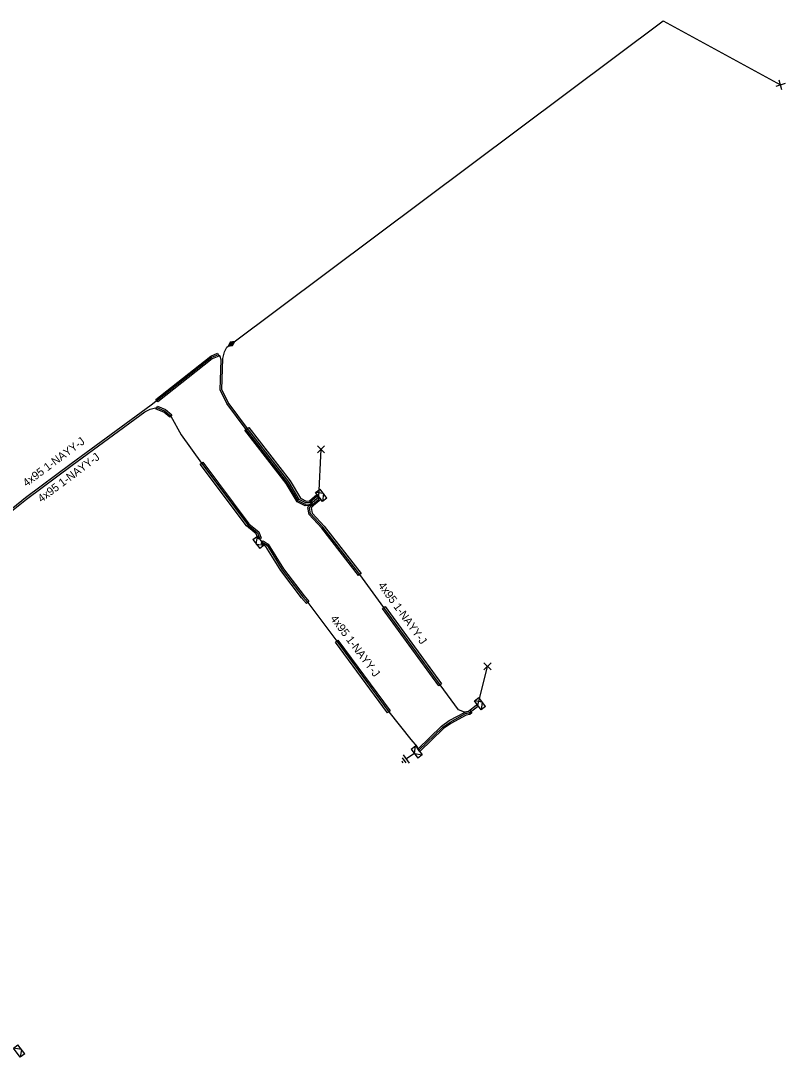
# Model space of a CAD drawing. Extents: x -544780 to -541582, y -1198995 to -1196551.
# Drawn here: x -543484.1 to -543388.6, y -1197308.9 to -1197179.5 of the extents above; entities that cross this region are included whole.
import ezdxf

# ---------------------------------------------------------------- set-up
doc = ezdxf.new("R2010")
doc.units = 0
for name, color, linetype in [('Vrstva 1', 7, 'Continuous'), ('Vrstva 14', 7, 'Continuous'), ('Vrstva 15', 7, 'Continuous'), ('Vrstva 19', 7, 'Continuous'), ('Vrstva 20', 7, 'Continuous'), ('Vrstva 31', 7, 'Continuous'), ('Vrstva 34', 7, 'Continuous'), ('Vrstva 4', 7, 'Continuous'), ('Vrstva 5', 7, 'Continuous'), ('Vrstva 52', 7, 'Continuous'), ('Vrstva 59', 7, 'Continuous'), ('Vrstva 6', 7, 'Continuous'), ('Vrstva 9', 7, 'Continuous')]:
    doc.layers.add(name, color=color, linetype=linetype)

# ---------------------------------------------------------------- blocks, each defined once
blk = doc.blocks.new('NN870')
at = {"layer": 'Vrstva 4'}
for points in [[(0, -0.25), (0.5, 0), (0, 0.25), (-0.5, 0), (0, -0.25)], [(0.37, 0), (0, 0.19), (-0.36, 0), (0, -0.19), (0.37, 0)], [(0.24, 0), (0, 0.12), (-0.25, 0), (0, -0.12), (0.24, 0)], [(0.12, 0), (0, 0.06), (-0.13, 0), (0, -0.06), (0.12, 0)]]:
    blk.add_lwpolyline(points, dxfattribs=at)
blk = doc.blocks.new('NN800')
at = {"layer": 'Vrstva 1'}
for points in [[(-0.44, 0.44), (0.44, -0.44)], [(-0.44, -0.44), (0.44, 0.44)]]:
    blk.add_lwpolyline(points, dxfattribs=at)
blk = doc.blocks.new('NN630')
at = {"layer": 'Vrstva 9'}
for points in [[(0, -0.7), (-0.7, 0)], [(-0.7, -0.7), (-0.7, 0), (0.7, 0), (0.7, -0.7)], [(-0.7, -0.7), (0.7, -0.7)], [(0, -0.7), (0.7, 0)]]:
    blk.add_lwpolyline(points, dxfattribs=at)
blk = doc.blocks.new('NN810')
at = {"layer": 'Vrstva 14'}
for points in [[(0, -0.64), (0, -1.89)], [(0.63, -1.89), (-0.62, -1.89)], [(0.39, -2.2), (-0.4, -2.2)], [(0, -2.52), (-0.12, -2.52)], [(0.14, -2.52), (0, -2.52)]]:
    blk.add_lwpolyline(points, dxfattribs=at)

msp = doc.modelspace()

# ---------------------------------------------------------------- linework, layer by layer
at = {"layer": 'Vrstva 20'}
for points in [[(-543459.33, -1197221.38), (-543460.15, -1197221.7), (-543466.96, -1197227.08), (-543467.21, -1197226.76), (-543460.35, -1197221.36), (-543459.49, -1197221)], [(-543467, -1197227.6), (-543466, -1197228.02), (-543465.2, -1197228.69), (-543465.46, -1197228.99), (-543466.22, -1197228.36), (-543467.16, -1197227.96)], [(-543447.75, -1197240.02), (-543448.57, -1197240.07), (-543449.57, -1197239.56), (-543450.94, -1197237.27), (-543456.09, -1197230.62), (-543455.61, -1197230.26), (-543450.44, -1197236.93), (-543449.15, -1197239.1), (-543448.45, -1197239.47), (-543447.79, -1197239.42)], [(-543461.34, -1197234.6), (-543455.58, -1197242.28), (-543454.34, -1197243.29), (-543454.05, -1197244.07), (-543454.43, -1197244.21), (-543454.68, -1197243.53), (-543455.88, -1197242.56), (-543461.66, -1197234.84)], [(-543446.58, -1197239.26), (-543447.52, -1197240.03), (-543448.02, -1197239.41), (-543447.08, -1197238.64)], [(-543441.88, -1197248.76), (-543446.49, -1197242.86), (-543448.06, -1197241.15), (-543448.23, -1197240.27), (-543448.11, -1197240), (-543447.77, -1197239.72), (-543447.52, -1197240.03), (-543447.78, -1197240.25), (-543447.81, -1197240.31), (-543447.68, -1197240.97), (-543446.19, -1197242.6), (-543441.56, -1197248.52)], [(-543453.81, -1197244.41), (-543453.16, -1197244.84), (-543451.26, -1197247.92), (-543448.69, -1197251.29), (-543448.09, -1197252.01), (-543448.39, -1197252.27), (-543449.01, -1197251.55), (-543451.6, -1197248.14), (-543453.46, -1197245.12), (-543454.03, -1197244.75)], [(-543431.86, -1197262.54), (-543435.56, -1197257.45), (-543438.89, -1197252.88), (-543438.57, -1197252.64), (-543435.24, -1197257.21), (-543431.54, -1197262.3)], [(-543444.46, -1197256.83), (-543437.95, -1197265.65), (-543438.27, -1197265.89), (-543444.78, -1197257.07)], [(-543434.5, -1197270.44), (-543431.55, -1197267.57), (-543430.57, -1197266.88), (-543428.59, -1197265.8), (-543428.18, -1197265.72), (-543428, -1197265.59), (-543427.76, -1197265.91), (-543428.01, -1197266.1), (-543428.46, -1197266.18), (-543430.35, -1197267.22), (-543431.29, -1197267.87), (-543434.22, -1197270.72)]]:
    msp.add_lwpolyline(points, close=True, dxfattribs=at)
at = {"layer": 'Vrstva 5'}
msp.add_lwpolyline([(-543486.07, -1197241.4), (-543483.36, -1197239.23), (-543477.66, -1197234.96), (-543468.59, -1197228.31), (-543467.93, -1197227.99), (-543467.08, -1197227.78), (-543466.11, -1197228.19), (-543465.33, -1197228.84), (-543464.03, -1197231.19), (-543461.5, -1197234.72), (-543455.73, -1197242.42), (-543454.51, -1197243.41), (-543454.24, -1197244.14), (-543454.1, -1197244.41), (-543453.92, -1197244.58), (-543453.31, -1197244.98), (-543451.43, -1197248.03), (-543448.85, -1197251.42), (-543448.24, -1197252.14), (-543444.62, -1197256.95), (-543438.11, -1197265.77), (-543435.38, -1197269.25), (-543434.58, -1197270.16), (-543434.36, -1197270.58), (-543431.42, -1197267.72), (-543430.46, -1197267.05), (-543428.52, -1197265.99), (-543428.09, -1197265.91), (-543427.08, -1197265.16), (-543427, -1197264.98), (-543427.2, -1197265), (-543428.18, -1197265.72), (-543428.68, -1197265.82), (-543429.43, -1197265.52), (-543431.7, -1197262.42), (-543435.4, -1197257.33), (-543438.73, -1197252.76), (-543441.72, -1197248.64), (-543446.34, -1197242.73), (-543447.87, -1197241.06), (-543448.02, -1197240.29), (-543447.95, -1197240.12), (-543446.83, -1197239.21), (-543446.83, -1197238.95), (-543447.9, -1197239.83), (-543448.53, -1197239.87), (-543449.43, -1197239.41), (-543450.77, -1197237.16), (-543455.93, -1197230.5), (-543458.35, -1197227.26), (-543459.18, -1197225.56), (-543459.03, -1197221.82), (-543459.15, -1197221.39), (-543459.41, -1197221.19), (-543460.25, -1197221.53), (-543467.78, -1197227.47), (-543477.78, -1197234.8), (-543483.48, -1197239.07), (-543486.19, -1197241.24)], dxfattribs=at)
at = {"layer": 'Vrstva 52'}
msp.add_lwpolyline([(-543446.83, -1197238.95), (-543447.09, -1197238.9), (-543447.98, -1197239.63), (-543448.49, -1197239.67), (-543449.29, -1197239.25), (-543450.61, -1197237.04), (-543455.77, -1197230.38), (-543458.17, -1197227.16), (-543458.98, -1197225.52), (-543458.82, -1197221.65), (-543458.61, -1197220.81), (-543458.32, -1197220.23), (-543457.76, -1197219.82)], dxfattribs=at)
at = {"layer": 'Vrstva 59'}
for points in [[(-543457.76, -1197219.82), (-543403.84, -1197179.47), (-543389.21, -1197187.49)], [(-543446.83, -1197238.95), (-543446.57, -1197232.99)], [(-543427, -1197264.98), (-543425.79, -1197260.11)]]:
    msp.add_lwpolyline(points, dxfattribs=at)

# ---------------------------------------------------------------- block references
at = {"layer": 'Vrstva 15', "rotation": -54.81533190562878}
msp.add_blockref('NN810', (-543434.36, -1197270.58), dxfattribs=at)
at = {"layer": 'Vrstva 19', "rotation": -143.79054322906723}
msp.add_blockref('NN870', (-543457.76, -1197219.82), dxfattribs=at)
at = {"layer": 'Vrstva 31'}
for p, rotation in [((-543446.83, -1197238.95), 127.17916552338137), ((-543454.1, -1197244.41), -52.91500930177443), ((-543427, -1197264.98), 126.99015354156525), ((-543434.36, -1197270.58), -52.86299036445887), ((-543484.55, -1197308.36), 127.11108553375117)]:
    msp.add_blockref('NN630', p, dxfattribs=dict(at, rotation=rotation))
at = {"layer": 'Vrstva 34', "rotation": 151.24371944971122}
msp.add_blockref('NN800', (-543389.21, -1197187.49), dxfattribs=at)
at = {"layer": 'Vrstva 34'}
for p in [(-543446.57, -1197232.99), (-543425.79, -1197260.11)]:
    msp.add_blockref('NN800', p, dxfattribs=at)

# ---------------------------------------------------------------- texts
at = {"layer": 'Vrstva 6'}
for rotation, p in [(36.839, (-543483.35, -1197237.72)), (36.836, (-543481.49, -1197239.68)), (305.969, (-543439.5, -1197250)), (306.965, (-543445.47, -1197254.16))]:
    msp.add_text('4x95 1-NAYY-J', height=1, rotation=rotation, dxfattribs=at).set_placement(p)

doc.saveas('drawing.dxf')
